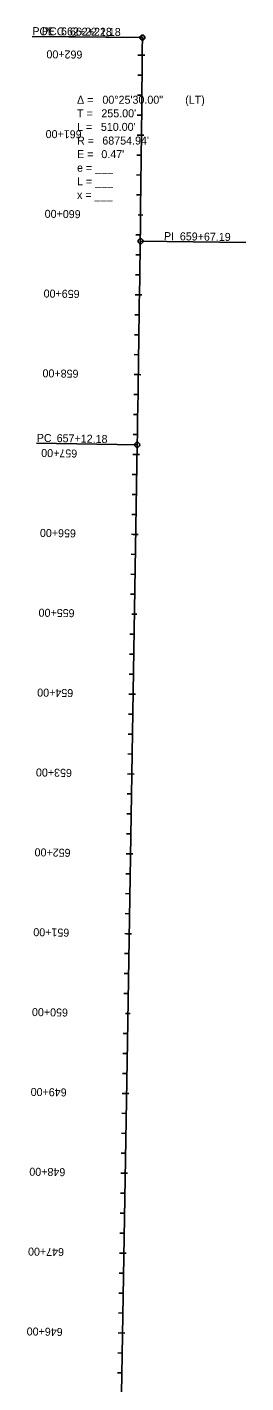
# Model space of a CAD drawing. Extents: x 23417911 to 23421158, y 6737892 to 6791804.
# Drawn here: x 23420631 to 23420905, y 6790106 to 6791804 of the extents above; entities that cross this region are included whole.
import ezdxf

# ---------------------------------------------------------------- set-up
doc = ezdxf.new("R2010")
doc.units = 0
for name, color, linetype in [('Alignment', 7, 'Continuous'), ('TextAlignment', 7, 'Continuous'), ('TextAlignmentLrg', 7, 'Continuous'), ('TextAlignmentSml', 7, 'Continuous')]:
    doc.layers.add(name, color=color, linetype=linetype)

msp = doc.modelspace()

# ---------------------------------------------------------------- linework, layer by layer
at = {"layer": 'Alignment'}
for p, q in [((23420756.2, 6790533.4), (23420768.5, 6791280.7)), ((23420756.2, 6790533.4), (23420768.5, 6791280.7)), ((23420743.8, 6789786.1), (23420756.2, 6790533.4)), ((23420743.8, 6789786.1), (23420756.2, 6790533.4))]:
    msp.add_line(p, q, dxfattribs=at)
msp.add_arc((23352023, 6792417.7), 68754.9, 359.052469, 359.477469, dxfattribs=at)
msp.add_arc((23352023, 6792417.7), 68754.9, 359.052469, 359.477469, dxfattribs=at)
at = {"layer": 'TextAlignment'}
for p, q in [((23420775.1, 6791790.6), (23420637.1, 6791791.9)), ((23420637.1, 6791791.9), (23420637.1, 6791791.9)), ((23420775.1, 6791790.6), (23420649.1, 6791791.8)), ((23420649.1, 6791791.8), (23420649.1, 6791791.8)), ((23420772.7, 6791535.6), (23420904.7, 6791533.9)), ((23420904.7, 6791533.9), (23420904.7, 6791533.9)), ((23420768.5, 6791280.7), (23420642.5, 6791282.8)), ((23420642.5, 6791282.8), (23420642.5, 6791282.8))]:
    msp.add_line(p, q, dxfattribs=at)
for centre, radius in [((23420775.1, 6791790.6), 3.12), ((23420775.1, 6791790.6), 2.67), ((23420772.7, 6791535.6), 3.12), ((23420768.5, 6791280.7), 3.12)]:
    msp.add_circle(centre, radius, dxfattribs=at)
at = {"layer": 'TextAlignmentLrg'}
for p, q in [((23420774.9, 6791768.4), (23420769.4, 6791768.5)), ((23420773.8, 6791668.4), (23420768.4, 6791668.5)), ((23420769.6, 6791568.5), (23420775.7, 6791568.4)), ((23420771.4, 6791468.5), (23420765.9, 6791468.5)), ((23420769.9, 6791368.5), (23420764.5, 6791368.6)), ((23420768.3, 6791268.5), (23420762.9, 6791268.6)), ((23420766.7, 6791168.5), (23420761.2, 6791168.6)), ((23420761.9, 6791068.6), (23420768.1, 6791068.5)), ((23420763.4, 6790968.5), (23420757.9, 6790968.6)), ((23420761.7, 6790868.5), (23420756.2, 6790868.6)), ((23420760, 6790768.6), (23420754.6, 6790768.6)), ((23420758.4, 6790668.6), (23420752.9, 6790668.7)), ((23420753.7, 6790568.6), (23420759.8, 6790568.5)), ((23420755.1, 6790468.6), (23420749.6, 6790468.7)), ((23420753.4, 6790368.6), (23420748, 6790368.7)), ((23420751.8, 6790268.6), (23420746.3, 6790268.7)), ((23420750.1, 6790168.6), (23420744.7, 6790168.7))]:
    msp.add_line(p, q, dxfattribs=at)
at = {"layer": 'TextAlignmentSml'}
for p, q in [((23420771.8, 6791768.5), (23420777.9, 6791768.4)), ((23420774.6, 6791743.4), (23420769.2, 6791743.5)), ((23420774.4, 6791718.4), (23420768.9, 6791718.5)), ((23420774.1, 6791693.4), (23420768.6, 6791693.5)), ((23420770.8, 6791668.5), (23420776.9, 6791668.4)), ((23420773.6, 6791643.4), (23420768.1, 6791643.5)), ((23420773.3, 6791618.4), (23420767.8, 6791618.5)), ((23420773, 6791593.5), (23420767.5, 6791593.5)), ((23420769.6, 6791568.5), (23420775.7, 6791568.4)), ((23420772.4, 6791543.5), (23420766.9, 6791543.5)), ((23420772, 6791518.5), (23420766.6, 6791518.5)), ((23420771.7, 6791493.5), (23420766.2, 6791493.5)), ((23420768.3, 6791468.5), (23420774.4, 6791468.4)), ((23420771, 6791443.5), (23420765.6, 6791443.5)), ((23420770.7, 6791418.5), (23420765.2, 6791418.5)), ((23420770.3, 6791393.5), (23420764.8, 6791393.6)), ((23420766.9, 6791368.5), (23420773, 6791368.4)), ((23420769.5, 6791343.5), (23420764.1, 6791343.6)), ((23420769.1, 6791318.5), (23420763.7, 6791318.6)), ((23420768.7, 6791293.5), (23420763.3, 6791293.6)), ((23420765.3, 6791268.5), (23420771.4, 6791268.4)), ((23420767.9, 6791243.5), (23420762.4, 6791243.6)), ((23420767.5, 6791218.5), (23420762, 6791218.6)), ((23420767.1, 6791193.5), (23420761.6, 6791193.6)), ((23420763.6, 6791168.5), (23420769.7, 6791168.4)), ((23420766.2, 6791143.5), (23420760.8, 6791143.6)), ((23420765.8, 6791118.5), (23420760.4, 6791118.6)), ((23420765.4, 6791093.5), (23420760, 6791093.6)), ((23420761.9, 6791068.6), (23420768.1, 6791068.5)), ((23420764.6, 6791043.5), (23420759.1, 6791043.6)), ((23420764.2, 6791018.5), (23420758.7, 6791018.6)), ((23420763.8, 6790993.5), (23420758.3, 6790993.6)), ((23420760.3, 6790968.6), (23420766.4, 6790968.5)), ((23420762.9, 6790943.5), (23420757.5, 6790943.6)), ((23420762.5, 6790918.5), (23420757.1, 6790918.6)), ((23420762.1, 6790893.5), (23420756.7, 6790893.6)), ((23420758.6, 6790868.6), (23420764.8, 6790868.5)), ((23420761.3, 6790843.5), (23420755.8, 6790843.6)), ((23420760.9, 6790818.5), (23420755.4, 6790818.6)), ((23420760.5, 6790793.5), (23420755, 6790793.6)), ((23420757, 6790768.6), (23420763.1, 6790768.5)), ((23420759.6, 6790743.6), (23420754.2, 6790743.6)), ((23420759.2, 6790718.6), (23420753.8, 6790718.7)), ((23420758.8, 6790693.6), (23420753.3, 6790693.7)), ((23420755.3, 6790668.6), (23420761.5, 6790668.5)), ((23420758, 6790643.6), (23420752.5, 6790643.7)), ((23420757.6, 6790618.6), (23420752.1, 6790618.7)), ((23420757.2, 6790593.6), (23420751.7, 6790593.7)), ((23420753.7, 6790568.6), (23420759.8, 6790568.5)), ((23420756.3, 6790543.6), (23420750.9, 6790543.7)), ((23420755.9, 6790518.6), (23420750.5, 6790518.7)), ((23420755.5, 6790493.6), (23420750, 6790493.7)), ((23420752, 6790468.6), (23420758.1, 6790468.5)), ((23420754.7, 6790443.6), (23420749.2, 6790443.7)), ((23420754.3, 6790418.6), (23420748.8, 6790418.7)), ((23420753.8, 6790393.6), (23420748.4, 6790393.7)), ((23420750.4, 6790368.7), (23420756.5, 6790368.6)), ((23420753, 6790343.6), (23420747.6, 6790343.7)), ((23420752.6, 6790318.6), (23420747.1, 6790318.7)), ((23420752.2, 6790293.6), (23420746.7, 6790293.7)), ((23420748.7, 6790268.7), (23420754.8, 6790268.6)), ((23420751.4, 6790243.6), (23420745.9, 6790243.7)), ((23420750.9, 6790218.6), (23420745.5, 6790218.7)), ((23420750.5, 6790193.6), (23420745.1, 6790193.7)), ((23420747.1, 6790168.7), (23420753.2, 6790168.6)), ((23420749.7, 6790143.6), (23420744.2, 6790143.7)), ((23420749.3, 6790118.6), (23420743.8, 6790118.7))]:
    msp.add_line(p, q, dxfattribs=at)

# ---------------------------------------------------------------- texts
at = {"layer": 'TextAlignment'}
for s, rotation, p in [('POE ', 359.4775, (23420637.1, 6791793.6)), ('PCC', 359.4775, (23420649.1, 6791793.5)), ('662+22.18', 359.4775, (23420673, 6791793.3)), ('662+22.18', 359.4775, (23420684.1, 6791793.1)), ('PI ', 359.265, (23420802, 6791537)), ('659+67.19', 359.265, (23420821.9, 6791536.7)), ('PC', 359.0525, (23420642.6, 6791284.4)), ('657+12.18', 359.0525, (23420667.5, 6791284))]:
    msp.add_text(s, height=10.02, rotation=rotation, dxfattribs=at).set_placement(p)
for s, p in [('Δ = ', (23420693.1, 6791707.7)), ('00°25\'30.00"', (23420724.9, 6791707.7)), (' (LT)', (23420824.9, 6791707.7)), ('T = ', (23420693.1, 6791690.7)), ("255.00'", (23420723.6, 6791690.7)), ('L = ', (23420693.1, 6791673.7)), ("510.00'", (23420723, 6791673.7)), ('R = ', (23420693.1, 6791656.6)), ("68754.94'", (23420724.8, 6791656.6)), ('E = ', (23420693.1, 6791639.6)), ("0.47'", (23420723.6, 6791639.6)), ('e = ___ ', (23420693.1, 6791622.6)), ('L = ___', (23420693.1, 6791605.5)), ('x = ___', (23420693.1, 6791588.5))]:
    msp.add_text(s, height=10.02, dxfattribs=at).set_placement(p)
at = {"layer": 'TextAlignmentLrg'}
for s, rotation, p in [('660+00', 179.2923, (23420697.7, 6791574.4)), ('655+00', 179.0525, (23420690.1, 6791074.8)), ('650+00', 179.0525, (23420681.8, 6790574.8))]:
    msp.add_text(s, height=10.02, rotation=rotation, dxfattribs=at).set_placement(p)
at = {"layer": 'TextAlignmentSml'}
for s, rotation, p in [('662+00', 179.459, (23420699.9, 6791774.2)), ('661+00', 179.3756, (23420698.9, 6791674.3)), ('660+00', 179.2923, (23420697.7, 6791574.4)), ('659+00', 179.209, (23420696.4, 6791474.5)), ('658+00', 179.1256, (23420695, 6791374.6)), ('657+00', 179.0525, (23420693.4, 6791274.7)), ('656+00', 179.0525, (23420691.8, 6791174.7)), ('655+00', 179.0525, (23420690.1, 6791074.8)), ('654+00', 179.0525, (23420688.4, 6790974.8)), ('653+00', 179.0525, (23420686.8, 6790874.8)), ('652+00', 179.0525, (23420685.1, 6790774.8)), ('651+00', 179.0525, (23420683.5, 6790674.8)), ('650+00', 179.0525, (23420681.8, 6790574.8)), ('649+00', 179.0525, (23420680.2, 6790474.8)), ('648+00', 179.0525, (23420678.5, 6790374.9)), ('647+00', 179.0525, (23420676.9, 6790274.9)), ('646+00', 179.0525, (23420675.2, 6790174.9))]:
    msp.add_text(s, height=10.02, rotation=rotation, dxfattribs=at).set_placement(p)

doc.saveas('drawing.dxf')
